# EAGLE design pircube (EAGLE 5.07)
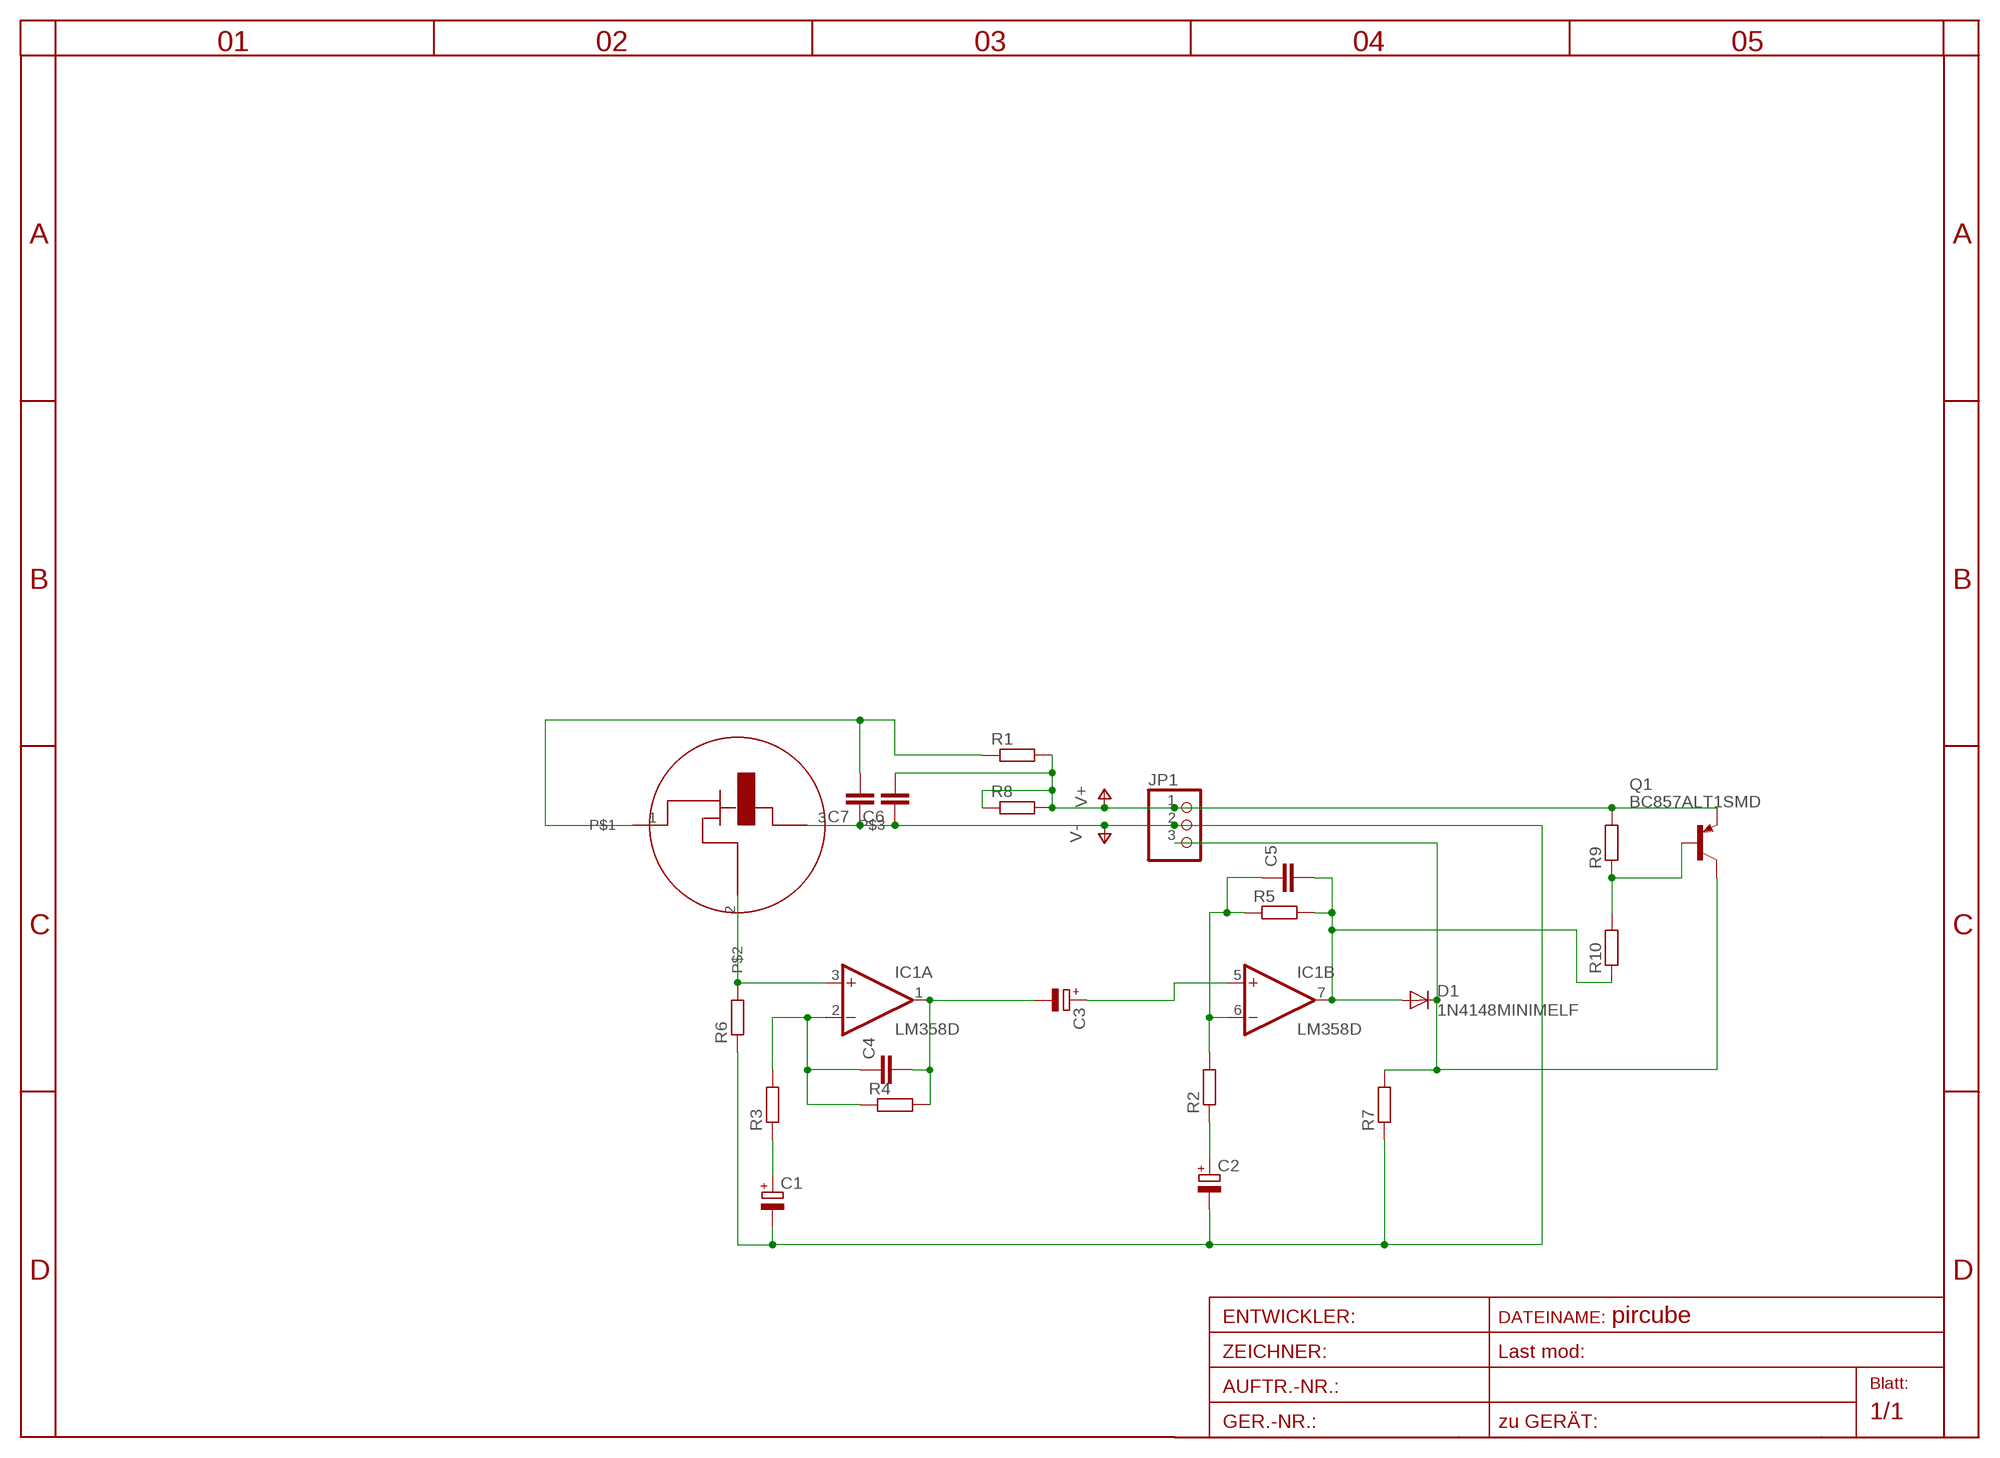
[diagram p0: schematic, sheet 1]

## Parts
C1  CPOL-EUE2.5-5  [E2,5-5]
C2  CPOL-EUE2.5-5  [E2,5-5]
C3  CPOL-EUE2.5-5  [E2,5-5]
C4  C-EUC0805  [C0805]
C5  C-EUC0805  [C0805]
C6  C-EUC0805  [C0805]
C7  C-EUC0805  [C0805]
D1  1N4148MINIMELF  [MINIMELF]
IC1  LM358D  [SO08]
JP1  PINHD-1X3  [1X03]
Q1  BC857ALT1SMD  [SOT23-BEC]
R1  R-EU_R0805  [R0805]
R2  R-EU_R0805  [R0805]
R3  R-EU_R1206  [R1206]
R4  R-EU_R0805  [R0805]
R5  R-EU_R0805  [R0805]
R6  R-EU_R0805  [R0805]
R7  R-EU_R0805  [R0805]
R8  R-EU_M1206  [M1206]
R9  R-EU_R0805  [R0805]
R10  R-EU_R1206  [R1206]
U$1  RE200B  [R200B]

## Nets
N$1: C5.2 D1.A IC1.7(B:OUT) R5.2 R10.1
N$3: C7.2 R1.1 U$1.1
N$4: IC1.3(A:+IN) R6.2 U$1.2
N$5: C4.1 IC1.2(A:-IN) R3.2 R4.1
N$6: C1.+ R3.1
N$7: C3.- C4.2 IC1.1(A:OUT) R4.2
N$8: C3.+ IC1.5(B:+IN)
N$9: C5.1 IC1.6(B:-IN) R2.2 R5.1
N$10: C2.+ R2.1
N$12: Q1.B R9.1 R10.2
SIGNAL: D1.C JP1.3 Q1.C R7.2
V+: C6.2 JP1.1 Q1.E R1.2 R8.1 R8.2 R9.2
V-: C1.- C2.- C6.1 C7.1 JP1.2 R6.1 R7.1 U$1.3

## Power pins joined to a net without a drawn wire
V+: IC1.8(P:V+)
V-: IC1.4(P:V-)

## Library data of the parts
C1-C3 = rcl:CPOL-EU: POLARIZED CAPACITOR, European symbol
C4-C7 = rcl:C-EU: CAPACITOR, European symbol
D1 = diode-1:1N4148: DIODE
IC1 = linear:LM358: OP AMP also LM158; LM258; LM2904 Source: http://cache.national.com/ds/LM/LM158.pdf
JP1 = pinhead:PINHD-1X3: PIN HEADER
Q1 = transistor-pnp:BC857*: PNP Transistror
R1-R10 = rcl:R-EU_: RESISTOR, European symbol
U$1 = photo-elements:RE200B

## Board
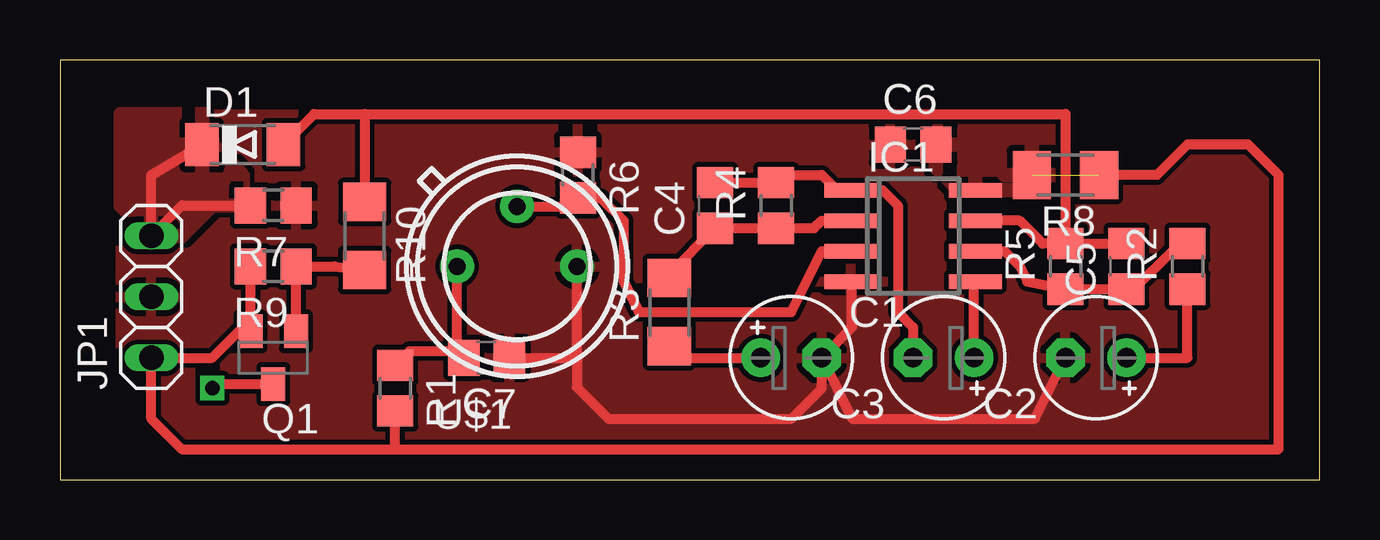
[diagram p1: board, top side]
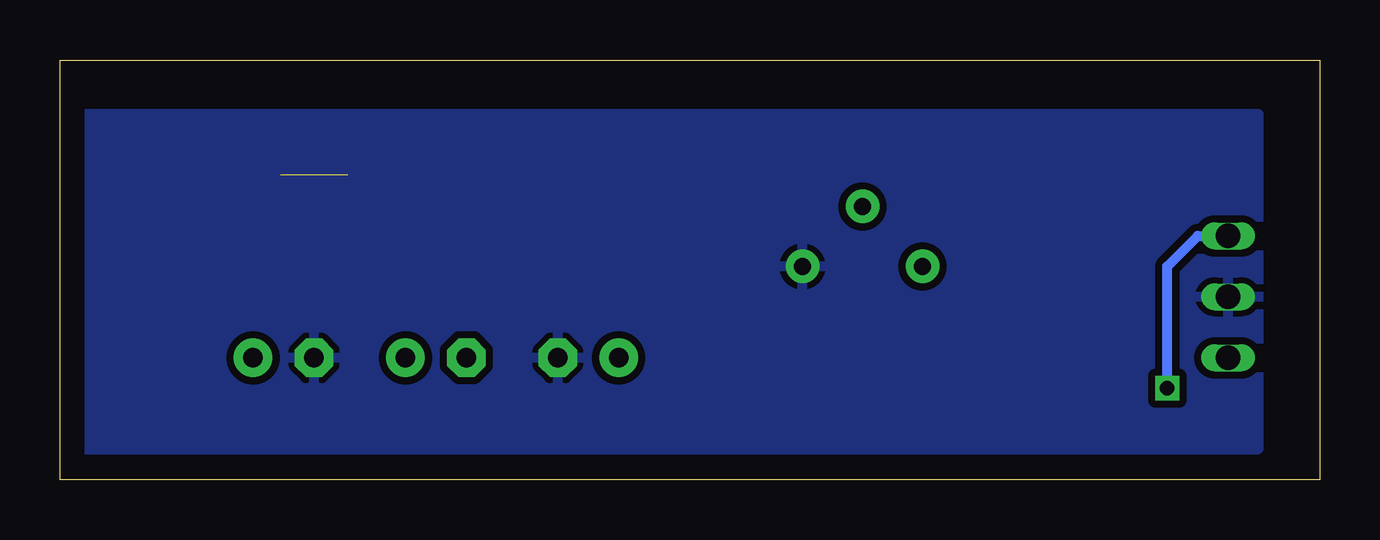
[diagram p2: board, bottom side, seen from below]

Size 52.5 x 17.5 mm. Coordinates in mm from the lower left corner, seen from the top.
Outline: 0,0 52.5,0 52.5,17.5 0,17.5 0,0
Copper layers (1*16): Top 0.035mm / dielectric 1.5mm / Bottom 0.035mm
Design rules "default": minimum track width 10mil, minimum drill 20mil, track to track 8mil, track to pad 8mil, pad to pad 8mil, via to via 8mil, smd to smd 8mil, copper to edge 40mil, drill to drill 8mil, minimum pad ring 1mil, minimum via ring 8mil, stop-mask expansion 4mil, vias tented up to drill 0mil, thermal gap 10mil

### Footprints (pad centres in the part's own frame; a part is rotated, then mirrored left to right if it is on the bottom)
E2,5-5 = drill 0.813 pad 1.6 round: + -1.27,0 | drill 0.813 pad 1.6 octagon: - 1.27,0
C0805 = smd 1.3 x 1.5: 1 -0.95,0; 2 0.95,0
MINIMELF = smd 1.4 x 1.8: A 1.7,0; C -1.7,0
SO08 = smd 0.6 x 2.2: 1 -1.905,-2.6; 2 -0.635,-2.6; 3 0.635,-2.6; 4 1.905,-2.6; 5 1.905,2.6; 6 0.635,2.6; 7 -0.635,2.6; 8 -1.905,2.6
1X03 = drill 1.016 long: 1 -2.54,0; 2 0,0; 3 2.54,0
SOT23-BEC = smd 1 x 1.4: B -0.95,-1.1; C 0,1.1; E 0.95,-1.1
R0805 = smd 1.3 x 1.5: 1 -0.95,0; 2 0.95,0
R1206 = smd 1.6 x 1.803: 1 -1.422,0; 2 1.422,0
M1206 = smd 1.6 x 2: 1 -1.4,0; 2 1.4,0
R200B = drill 0.7 pad 1.4 round: 1 -2.5,0; 2 0,2.5; 3 2.5,0

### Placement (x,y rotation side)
C1  30.48,5.08 0 top
C2  43.18,5.08 180 top
C3  36.83,5.08 180 top
C4  27.3,11.43 90 top
C5  44.45,8.89 90 top
C6  35.56,13.97 0 top
C7  17.78,5.08 180 top
D1  7.62,13.97 0 top
IC1  35.56,10.16 270 top
JP1  3.81,7.62 90 top
Q1  8.89,5.08 180 top
R1  13.97,3.81 270 top
R2  46.99,8.89 90 top
R3  25.4,6.99 90 top
R4  29.84,11.43 90 top
R5  41.91,8.89 90 top
R6  21.59,12.7 270 top
R7  8.89,11.43 180 top
R8  41.91,12.7 180 top
R9  8.89,8.89 180 top
R10  12.7,10.16 270 top
U$1  19.05,8.89 0 top

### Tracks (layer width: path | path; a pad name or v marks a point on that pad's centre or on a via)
N$1
  Top 0.406: R5.2 41.91,15.24 12.7,15.24 | R5.2 C5.2 | R5.2 40.96,9.84 40.01,10.79 IC1.7 | 12.7,15.24 10.59,15.24 D1.A | 12.7,15.24 R10.1
N$3
  Top 0.406: 16.55,5.36 U$1.1 | 16.55,5.36 C7.2 | 16.55,5.36 14.57,5.36 R1.1
N$4
  Top 0.406: IC1.3 31.75,9.53 30.48,6.99 24.13,6.99 23.5,8.26 23.5,10.79 22.54,11.75 R6.2 21.23,11.39 U$1.2
N$5
  Top 0.406: R3.2 25.4,8.57 C4.1 R4.1 31.43,10.48 31.75,10.79 IC1.2
N$6
  Top 0.406: C1.+ 25.72,5.08 R3.1
N$7
  Top 0.406: C3.- 35.56,6.35 34.92,6.99 34.92,11.43 34.29,12.06 IC1.1 32.38,12.06 31.75,12.7 30.16,12.7 R4.2 C4.2
N$8
  Top 0.406: C3.+ 38.1,8.2 IC1.5
N$9
  Top 0.406: IC1.6 39.37,9.53 40.01,8.89 40.32,8.26 R5.1 C5.1 44.77,7.94 46.35,9.53 46.67,9.53 R2.2
N$10
  Top 0.406: C2.+ 46.99,5.08 R2.1
N$12
  Top 0.406: R10.2 11.43,8.89 R9.1 Q1.B
SIGNAL  (via drill 0.6)
  Top 0.406: D1.C 3.81,12.7 JP1.3 5.08,11.43 R7.2 | Q1.C 6.52,3.98 v6.35,3.81
  Bottom 0.406: v6.35,3.81 6.35,8.89 5.08,10.16 JP1.3
  pour Top: 3.81,10.16 2.54,11.43 2.54,15.24 6.35,15.24 6.35,13.97 7.62,12.7 7.62,11.43 6.35,11.43 5.08,10.16
V+  (1 unrouted)
  Top 0.406: R8.1 45.72,12.7 46.99,13.97 49.53,13.97 50.8,12.7 50.8,1.27 13.97,1.27 | R9.2 Q1.E 7.45,6.18 6.35,5.08 JP1.1 3.81,2.54 5.08,1.27 13.97,1.27 | 13.97,1.27 R1.2
  pour Top: 36.83,15.24 41.91,15.24 41.91,12.06 37.47,12.06 36.2,13.34
V-
  Top 0.406: 21.55,5.08 U$1.3 | 21.55,5.08 21.55,3.85 22.86,2.54 30.48,2.54 31.75,3.81 C1.- | C2.- 40.64,2.54 33.02,2.54 C1.- | C1.- 33.02,6.35 33.02,8.2 IC1.4 | C7.1 21.55,5.08
  pour Top (rank 2): 2.54,15.24 52.07,15.24 52.07,12.7 52.07,1.27 2.54,1.27 2.54,3.81
  pour Bottom (isolate 0.305): 2.54,15.24 52.07,15.24 52.07,12.7 52.07,1.27 2.54,1.27 2.54,3.81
